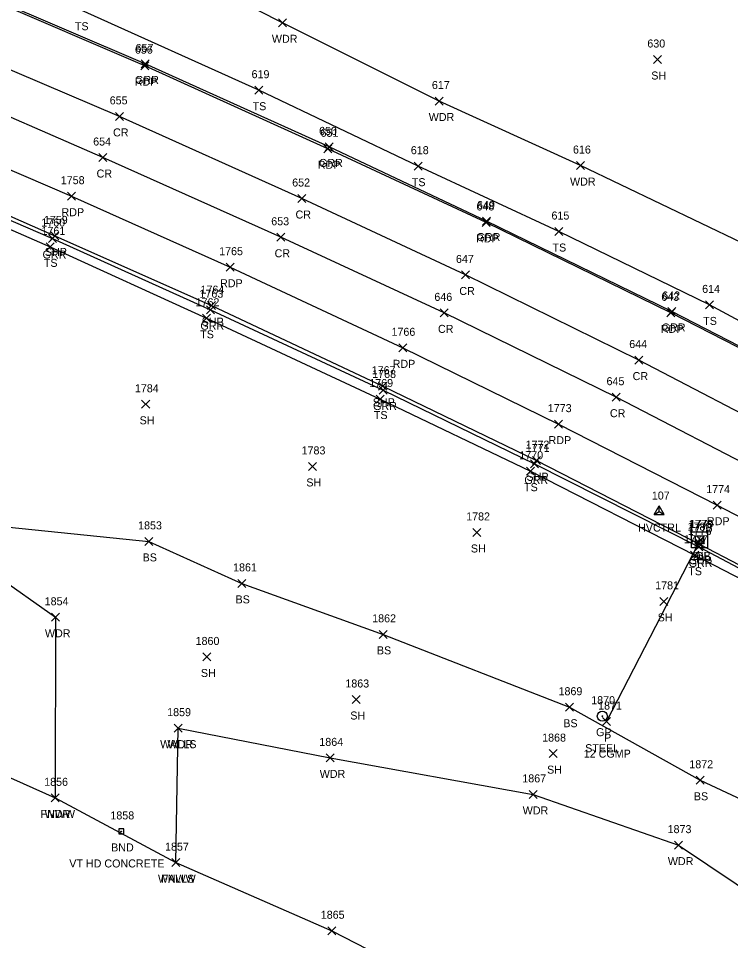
# Model space of a CAD drawing. Extents: x 1629176 to 1637209, y 606063 to 610167.
# Drawn here: x 1630257.8 to 1630435.7, y 606629.8 to 606860.2 of the extents above; entities that cross this region are included whole.
import ezdxf

# ---------------------------------------------------------------- set-up
doc = ezdxf.new("R2010")
doc.units = 0
for name, color, linetype in [('C_A', 7, 'Continuous'), ('C_I', 7, 'Continuous'), ('CPSM', 7, 'Continuous'), ('D_A', 7, 'Continuous'), ('D_C', 7, 'Continuous'), ('D_I', 7, 'Continuous'), ('D_TIC', 7, 'Continuous'), ('DCP', 7, 'Continuous'), ('DS', 7, 'Continuous'), ('L_A', 7, 'Continuous'), ('L_I', 7, 'Continuous'), ('L_TIC', 7, 'Continuous'), ('LAWA', 7, 'Continuous'), ('LELB', 7, 'Continuous'), ('LFNC', 7, 'Continuous'), ('LWS', 7, 'Continuous'), ('M_A', 7, 'Continuous'), ('M_C', 7, 'Continuous'), ('M_I', 7, 'Continuous'), ('MHBP', 7, 'Continuous'), ('P_A', 7, 'Continuous'), ('P_I', 7, 'Continuous'), ('P_TIC', 7, 'Continuous'), ('PET', 7, 'Continuous'), ('PRC', 7, 'Continuous'), ('PSP', 7, 'Continuous'), ('R_A', 7, 'Continuous'), ('R_C', 7, 'Continuous'), ('R_I', 7, 'Continuous'), ('R_TIC', 7, 'Continuous'), ('RGP', 7, 'Continuous'), ('RGR', 7, 'Continuous')]:
    doc.layers.add(name, color=color, linetype=linetype)

msp = doc.modelspace()

# ---------------------------------------------------------------- linework, layer by layer
at = {"layer": 'CPSM'}
for p, q in [((1630416.63, 606736.3), (1630417.88, 606738.46)), ((1630419.13, 606736.3), (1630417.88, 606738.46)), ((1630417.88, 606737.02), (1630417.88, 606738.46)), ((1630416.63, 606736.3), (1630417.88, 606737.02)), ((1630416.63, 606736.3), (1630419.13, 606736.3)), ((1630417.88, 606737.02), (1630417.88, 606737.02)), ((1630417.88, 606737.02), (1630419.13, 606736.3))]:
    msp.add_line(p, q, dxfattribs=at)
at = {"layer": 'D_TIC'}
for points in [[(1630427.15, 606728.94), (1630429.15, 606730.94)], [(1630429.15, 606728.94), (1630427.15, 606730.94)], [(1630426.71, 606728.26), (1630428.71, 606730.26)], [(1630428.71, 606728.26), (1630426.71, 606730.26)], [(1630403.72, 606683.54), (1630405.72, 606685.54)], [(1630405.72, 606683.54), (1630403.72, 606685.54)]]:
    msp.add_lwpolyline(points, dxfattribs=at)
at = {"layer": 'DCP'}
msp.add_lwpolyline([(1630427.71, 606729.26), (1630404.72, 606684.54)], dxfattribs=at)
at = {"layer": 'DS'}
for p, q in [((1630425.93, 606731.94), (1630429.93, 606731.94)), ((1630425.93, 606727.94), (1630425.93, 606731.94)), ((1630426.93, 606728.94), (1630426.93, 606730.94)), ((1630426.93, 606730.94), (1630428.93, 606730.94)), ((1630428.93, 606730.94), (1630428.93, 606728.94)), ((1630429.93, 606731.94), (1630429.93, 606727.94)), ((1630428.93, 606728.94), (1630426.93, 606728.94)), ((1630427.93, 606729.94), (1630427.93, 606729.94)), ((1630427.93, 606729.94), (1630427.93, 606729.94)), ((1630429.93, 606727.94), (1630425.93, 606727.94))]:
    msp.add_line(p, q, dxfattribs=at)
at = {"layer": 'L_TIC'}
for points in [[(1630322.76, 606858.13), (1630324.76, 606860.13)], [(1630324.76, 606858.13), (1630322.76, 606860.13)], [(1630416.39, 606848.96), (1630418.39, 606850.96)], [(1630418.39, 606848.96), (1630416.39, 606850.96)], [(1630316.9, 606841.29), (1630318.9, 606843.29)], [(1630318.9, 606841.29), (1630316.9, 606843.29)], [(1630361.92, 606838.59), (1630363.92, 606840.59)], [(1630363.92, 606838.59), (1630361.92, 606840.59)], [(1630356.66, 606822.31), (1630358.66, 606824.31)], [(1630358.66, 606822.31), (1630356.66, 606824.31)], [(1630397.22, 606822.46), (1630399.22, 606824.46)], [(1630399.22, 606822.46), (1630397.22, 606824.46)], [(1630391.8, 606805.98), (1630393.8, 606807.98)], [(1630393.8, 606805.98), (1630391.8, 606807.98)], [(1630264.76, 606802.15), (1630266.76, 606804.15)], [(1630266.76, 606802.15), (1630264.76, 606804.15)], [(1630429.43, 606787.65), (1630431.43, 606789.65)], [(1630431.43, 606787.65), (1630429.43, 606789.65)], [(1630303.81, 606784.31), (1630305.81, 606786.31)], [(1630305.81, 606784.31), (1630303.81, 606786.31)], [(1630347.18, 606764.13), (1630349.18, 606766.13)], [(1630349.18, 606764.13), (1630347.18, 606766.13)], [(1630288.6, 606762.82), (1630290.6, 606764.82)], [(1630290.6, 606762.82), (1630288.6, 606764.82)], [(1630330.23, 606747.3), (1630332.23, 606749.3)], [(1630332.23, 606747.3), (1630330.23, 606749.3)], [(1630384.69, 606746.11), (1630386.69, 606748.11)], [(1630386.69, 606746.11), (1630384.69, 606748.11)], [(1630371.34, 606730.8), (1630373.34, 606732.8)], [(1630373.34, 606730.8), (1630371.34, 606732.8)], [(1630289.4, 606728.57), (1630291.4, 606730.57)], [(1630291.4, 606728.57), (1630289.4, 606730.57)], [(1630425.71, 606725.12), (1630427.71, 606727.12)], [(1630427.71, 606725.12), (1630425.71, 606727.12)], [(1630312.6, 606718.08), (1630314.6, 606720.08)], [(1630314.6, 606718.08), (1630312.6, 606720.08)], [(1630417.98, 606713.59), (1630419.98, 606715.59)], [(1630419.98, 606713.59), (1630417.98, 606715.59)], [(1630266.08, 606709.61), (1630268.08, 606711.61)], [(1630268.08, 606709.61), (1630266.08, 606711.61)], [(1630347.91, 606705.34), (1630349.91, 606707.34)], [(1630349.91, 606705.34), (1630347.91, 606707.34)], [(1630303.9, 606699.7), (1630305.9, 606701.7)], [(1630305.9, 606699.7), (1630303.9, 606701.7)], [(1630341.21, 606689.07), (1630343.21, 606691.07)], [(1630343.21, 606689.07), (1630341.21, 606691.07)], [(1630394.46, 606687.14), (1630396.46, 606689.14)], [(1630396.46, 606687.14), (1630394.46, 606689.14)], [(1630296.68, 606681.91), (1630298.68, 606683.91)], [(1630298.68, 606681.91), (1630296.68, 606683.91)], [(1630296.68, 606681.91), (1630298.68, 606683.91)], [(1630298.68, 606681.91), (1630296.68, 606683.91)], [(1630390.36, 606675.55), (1630392.36, 606677.55)], [(1630392.36, 606675.55), (1630390.36, 606677.55)], [(1630334.71, 606674.48), (1630336.71, 606676.48)], [(1630336.71, 606674.48), (1630334.71, 606676.48)], [(1630427.07, 606668.89), (1630429.07, 606670.89)], [(1630429.07, 606668.89), (1630427.07, 606670.89)], [(1630266, 606664.5), (1630268, 606666.5)], [(1630268, 606664.5), (1630266, 606666.5)], [(1630266, 606664.5), (1630268, 606666.5)], [(1630268, 606664.5), (1630266, 606666.5)], [(1630385.4, 606665.36), (1630387.4, 606667.36)], [(1630387.4, 606665.36), (1630385.4, 606667.36)], [(1630421.65, 606652.68), (1630423.65, 606654.68)], [(1630423.65, 606652.68), (1630421.65, 606654.68)], [(1630296.13, 606648.31), (1630298.13, 606650.31)], [(1630298.13, 606648.31), (1630296.13, 606650.31)], [(1630296.13, 606648.31), (1630298.13, 606650.31)], [(1630298.13, 606648.31), (1630296.13, 606650.31)], [(1630335.07, 606631.29), (1630337.07, 606633.29)], [(1630337.07, 606631.29), (1630335.07, 606633.29)]]:
    msp.add_lwpolyline(points, dxfattribs=at)
at = {"layer": 'LAWA'}
for points in [[(1630313.82, 606946.86), (1630358.76, 606925.61), (1630402.3, 606903.75), (1630450.92, 606884.57), (1630493.61, 606863.97), (1630542.51, 606827.97), (1630547.78, 606801.97), (1630542.32, 606780.41), (1630525.99, 606758.91), (1630486.85, 606779.39), (1630438.5, 606804.18), (1630398.22, 606823.46), (1630362.92, 606839.59), (1630323.76, 606859.13), (1630280.39, 606881.23), (1630260.08, 606922.64), (1630278.57, 606959.7)], [(1630178.45, 606705.28), (1630189.54, 606725.28), (1630217.36, 606717.59), (1630251.89, 606721.32), (1630267.08, 606710.61), (1630267, 606665.5)], [(1630297.68, 606682.91), (1630335.71, 606675.48), (1630386.4, 606666.36), (1630422.65, 606653.68), (1630444.38, 606639.08), (1630446.66, 606637.81), (1630486.16, 606613.28), (1630514.89, 606608.05), (1630539.89, 606609.62), (1630562.09, 606603.08), (1630591.48, 606594.03), (1630626, 606578), (1630626.04, 606578.1), (1630670.33, 606553.73), (1630697.07, 606528.38), (1630722.88, 606501.58)]]:
    msp.add_lwpolyline(points, dxfattribs=at)
at = {"layer": 'LELB'}
for points in [[(1630772.3, 606583.26), (1630744.36, 606600.82), (1630702.09, 606628.01), (1630669.73, 606653.69), (1630639.16, 606677.6), (1630625.62, 606682.65), (1630575.5, 606708.79), (1630543.73, 606726.11), (1630517.88, 606742.14), (1630478.23, 606762.96), (1630430.43, 606788.65), (1630392.8, 606806.98), (1630357.66, 606823.31), (1630317.9, 606842.29), (1630273.51, 606862.27), (1630239.69, 606876.29), (1630209.67, 606888.82), (1630166.54, 606905.65), (1630125.1, 606921.22), (1630084.2, 606935.53), (1630049.16, 606947.36)], [(1630044.25, 606889.35), (1630091.41, 606872.59), (1630136.9, 606855.8), (1630181.87, 606838.43), (1630229.1, 606819.13), (1630265.76, 606803.15), (1630304.81, 606785.31), (1630348.18, 606765.13), (1630385.69, 606747.11), (1630426.71, 606726.12), (1630450.89, 606713.6)], [(1630053.59, 606794.16), (1630081.62, 606779.15), (1630106.52, 606768.08), (1630137.48, 606760.05), (1630167.15, 606751.57), (1630192.23, 606740.71), (1630218.23, 606736.11), (1630252.15, 606733.42), (1630290.4, 606729.57), (1630313.6, 606719.08), (1630348.91, 606706.34), (1630395.46, 606688.14), (1630428.07, 606669.89), (1630459.56, 606655.15)]]:
    msp.add_lwpolyline(points, dxfattribs=at)
at = {"layer": 'LFNC'}
msp.add_lwpolyline([(1630083.24, 606643.38), (1630104.82, 606668.58), (1630132.44, 606699.6), (1630148.03, 606717.8), (1630178.45, 606705.28), (1630206.32, 606692.67), (1630267, 606665.5), (1630297.13, 606649.31), (1630336.07, 606632.29), (1630377.56, 606610.95), (1630421.19, 606588.3), (1630449.11, 606572.58), (1630476.9, 606556.84), (1630504.46, 606540.78), (1630518.72, 606532.31), (1630544.56, 606516.77), (1630586.07, 606490.29), (1630617.62, 606470.71), (1630638.04, 606457.74), (1630683.84, 606426.78)], dxfattribs=at)
at = {"layer": 'LWS'}
msp.add_lwpolyline([(1630297.13, 606649.31), (1630297.68, 606682.91)], dxfattribs=at)
at = {"layer": 'MHBP'}
for p, q in [((1630284.13, 606657.77), (1630282.88, 606657.77)), ((1630282.88, 606657.77), (1630282.88, 606656.52)), ((1630284.13, 606657.77), (1630282.88, 606657.77)), ((1630282.88, 606657.77), (1630282.88, 606656.52)), ((1630284.13, 606656.52), (1630284.13, 606657.77)), ((1630284.13, 606656.52), (1630284.13, 606657.77)), ((1630282.88, 606656.52), (1630284.13, 606656.52)), ((1630282.88, 606656.52), (1630284.13, 606656.52))]:
    msp.add_line(p, q, dxfattribs=at)
msp.add_circle((1630283.48, 606657.11), 0.0833, dxfattribs=at)
at = {"layer": 'P_TIC'}
for points in [[(1630288.38, 606847.42), (1630290.38, 606849.42)], [(1630290.38, 606847.42), (1630288.38, 606849.42)], [(1630282.03, 606834.75), (1630284.03, 606836.75)], [(1630284.03, 606834.75), (1630282.03, 606836.75)], [(1630334.12, 606826.65), (1630336.12, 606828.65)], [(1630336.12, 606826.65), (1630334.12, 606828.65)], [(1630277.9, 606824.47), (1630279.9, 606826.47)], [(1630279.9, 606824.47), (1630277.9, 606826.47)], [(1630270.1, 606814.81), (1630272.1, 606816.81)], [(1630272.1, 606814.81), (1630270.1, 606816.81)], [(1630327.6, 606814.23), (1630329.6, 606816.23)], [(1630329.6, 606814.23), (1630327.6, 606816.23)], [(1630373.62, 606808.25), (1630375.62, 606810.25)], [(1630375.62, 606808.25), (1630373.62, 606810.25)], [(1630265.88, 606804.89), (1630267.88, 606806.89)], [(1630267.88, 606804.89), (1630265.88, 606806.89)], [(1630322.37, 606804.55), (1630324.37, 606806.55)], [(1630324.37, 606804.55), (1630322.37, 606806.55)], [(1630309.69, 606797.07), (1630311.69, 606799.07)], [(1630311.69, 606797.07), (1630309.69, 606799.07)], [(1630368.5, 606795.13), (1630370.5, 606797.13)], [(1630370.5, 606795.13), (1630368.5, 606797.13)], [(1630305.04, 606787.47), (1630307.04, 606789.47)], [(1630307.04, 606787.47), (1630305.04, 606789.47)], [(1630363.16, 606785.66), (1630365.16, 606787.66)], [(1630365.16, 606785.66), (1630363.16, 606787.66)], [(1630419.78, 606785.67), (1630421.78, 606787.67)], [(1630421.78, 606785.67), (1630419.78, 606787.67)], [(1630352.79, 606776.93), (1630354.79, 606778.93)], [(1630354.79, 606776.93), (1630352.79, 606778.93)], [(1630411.78, 606773.87), (1630413.78, 606775.87)], [(1630413.78, 606773.87), (1630411.78, 606775.87)], [(1630347.79, 606767.34), (1630349.79, 606769.34)], [(1630349.79, 606767.34), (1630347.79, 606769.34)], [(1630406.11, 606764.59), (1630408.11, 606766.59)], [(1630408.11, 606764.59), (1630406.11, 606766.59)], [(1630391.73, 606757.86), (1630393.73, 606759.86)], [(1630393.73, 606757.86), (1630391.73, 606759.86)], [(1630386.17, 606748.74), (1630388.17, 606750.74)], [(1630388.17, 606748.74), (1630386.17, 606750.74)], [(1630431.29, 606737.62), (1630433.29, 606739.62)], [(1630433.29, 606737.62), (1630431.29, 606739.62)], [(1630426.91, 606727.87), (1630428.91, 606729.87)], [(1630428.91, 606727.87), (1630426.91, 606729.87)]]:
    msp.add_lwpolyline(points, dxfattribs=at)
at = {"layer": 'PET'}
for points in [[(1630769.62, 606580.83), (1630742.32, 606598.72), (1630700.55, 606625.63), (1630665.45, 606648.34), (1630621.98, 606674.98), (1630606.18, 606684.39), (1630572.37, 606704.1), (1630541.12, 606722.17), (1630498.96, 606745.43), (1630457.51, 606767.81), (1630420.78, 606786.67), (1630374.62, 606809.25), (1630335.12, 606827.65), (1630289.38, 606848.42), (1630250.13, 606865.31), (1630203.69, 606884.49), (1630159.86, 606901.83), (1630115.59, 606918.47), (1630070.26, 606934.37)], [(1630050.76, 606901.68), (1630096.23, 606885.67), (1630143.35, 606868.08), (1630186.15, 606851.44), (1630235.05, 606831.31), (1630271.1, 606815.81), (1630310.69, 606798.07), (1630353.79, 606777.93), (1630392.73, 606758.86), (1630432.29, 606738.62), (1630464.02, 606722.09), (1630502.44, 606701.07), (1630537.98, 606680.83), (1630570.03, 606662.27), (1630609.11, 606638.58), (1630644.7, 606616.38), (1630681.38, 606592.72), (1630715.14, 606570.86), (1630750.81, 606547.81)]]:
    msp.add_lwpolyline(points, dxfattribs=at)
at = {"layer": 'PRC'}
for points in [[(1630762, 606568.31), (1630732.48, 606587.66), (1630693.14, 606613.4), (1630657.5, 606636.16), (1630615.44, 606661.97), (1630565.18, 606692.12), (1630533.4, 606710.56), (1630491.42, 606733.47), (1630450.45, 606755.19), (1630412.78, 606774.87), (1630369.5, 606796.13), (1630328.6, 606815.23), (1630283.03, 606835.75), (1630244.34, 606852.21), (1630197.18, 606871.73), (1630154.28, 606888.46), (1630110.18, 606905.77), (1630065.36, 606921.68)], [(1630755.45, 606559.52), (1630726, 606578.65), (1630686.27, 606604.3), (1630651.63, 606626.53), (1630610.5, 606651.79), (1630559.24, 606682.64), (1630527.45, 606700.94), (1630485.76, 606723.98), (1630445.96, 606745.41), (1630407.11, 606765.59), (1630364.16, 606786.66), (1630323.37, 606805.55), (1630278.9, 606825.47), (1630240.3, 606842.26), (1630192.63, 606861.5), (1630149.2, 606878.91), (1630105.99, 606894.95), (1630061.18, 606910.94)]]:
    msp.add_lwpolyline(points, dxfattribs=at)
at = {"layer": 'PSP'}
msp.add_lwpolyline([(1630045.28, 606892.75), (1630092.08, 606875.64), (1630138.49, 606858.75), (1630183.19, 606841.37), (1630230, 606822.13), (1630266.88, 606805.89), (1630306.04, 606788.47), (1630348.79, 606768.34), (1630387.17, 606749.74), (1630427.91, 606728.87), (1630457.64, 606713.36), (1630497.17, 606691.94), (1630531.87, 606672.45), (1630564.31, 606653.82), (1630602.72, 606629.92), (1630638.6, 606607.1), (1630675.39, 606583.77), (1630709.63, 606561.3), (1630744.78, 606538.28)], dxfattribs=at)
at = {"layer": 'R_TIC'}
for points in [[(1630288.48, 606847.85), (1630290.48, 606849.85)], [(1630290.48, 606847.85), (1630288.48, 606849.85)], [(1630334.39, 606827.12), (1630336.39, 606829.12)], [(1630336.39, 606827.12), (1630334.39, 606829.12)], [(1630373.76, 606808.6), (1630375.76, 606810.6)], [(1630375.76, 606808.6), (1630373.76, 606810.6)], [(1630265.36, 606804.24), (1630267.36, 606806.24)], [(1630267.36, 606804.24), (1630265.36, 606806.24)], [(1630304.77, 606786.45), (1630306.77, 606788.45)], [(1630306.77, 606786.45), (1630304.77, 606788.45)], [(1630420.01, 606786.01), (1630422.01, 606788.01)], [(1630422.01, 606786.01), (1630420.01, 606788.01)], [(1630347.91, 606766.39), (1630349.91, 606768.39)], [(1630349.91, 606766.39), (1630347.91, 606768.39)], [(1630385.68, 606747.91), (1630387.68, 606749.91)], [(1630387.68, 606747.91), (1630385.68, 606749.91)], [(1630426.72, 606727.18), (1630428.72, 606729.18)], [(1630428.72, 606727.18), (1630426.72, 606729.18)]]:
    msp.add_lwpolyline(points, dxfattribs=at)
at = {"layer": 'RGP'}
msp.add_line((1630403.65, 606685.9), (1630403.65, 606685.9), dxfattribs=at)
for radius in [1.25, 0.0833]:
    msp.add_circle((1630403.65, 606685.9), radius, dxfattribs=at)
at = {"layer": 'RGR'}
for points in [[(1630636.53, 606670.83), (1630623.24, 606676.36), (1630606.52, 606684.67), (1630573.19, 606704.3), (1630541.55, 606722.4), (1630499.19, 606745.82), (1630457.55, 606768.16), (1630421.01, 606787.01), (1630374.76, 606809.6), (1630335.39, 606828.12), (1630289.48, 606848.85), (1630250.07, 606865.82), (1630203.7, 606885.03), (1630160.01, 606902.28), (1630115.67, 606918.76), (1630070.66, 606934.74)], [(1630044.87, 606891.43), (1630091.95, 606875), (1630137.84, 606857.9), (1630182.67, 606840.57), (1630230.01, 606820.88), (1630266.36, 606805.24), (1630305.77, 606787.45), (1630348.91, 606767.39), (1630386.68, 606748.91), (1630427.72, 606728.18), (1630457.43, 606712.48), (1630496.65, 606691.24), (1630531.18, 606671.77), (1630563.73, 606652.86), (1630574.41, 606646.66), (1630584.49, 606638.94), (1630594.27, 606630.4)]]:
    msp.add_lwpolyline(points, dxfattribs=at)

# ---------------------------------------------------------------- texts
at = {"layer": 'C_A'}
msp.add_text('HVCTRL', height=2, dxfattribs=at).set_placement((1630412.58, 606732.02))
at = {"layer": 'C_I'}
msp.add_text('107', height=2, dxfattribs=at).set_placement((1630416.01, 606740.02))
at = {"layer": 'D_A'}
for s, p in [('DIB', (1630426.25, 606724.94)), ('DI', (1630426.99, 606724.94)), ('P', (1630427.08, 606724.26)), ('P', (1630404.09, 606679.54))]:
    msp.add_text(s, height=2, dxfattribs=at).set_placement(p)
at = {"layer": 'D_C'}
msp.add_text('12 CGMP', height=2, dxfattribs=at).set_placement((1630399.01, 606675.54))
at = {"layer": 'D_I'}
for s, p in [('1778', (1630425.24, 606732.94)), ('1779', (1630425.45, 606732.94)), ('1780', (1630424.93, 606732.26)), ('1871', (1630402.59, 606687.54))]:
    msp.add_text(s, height=2, dxfattribs=at).set_placement(p)
at = {"layer": 'L_A'}
for s, p in [('TS', (1630271.92, 606857.27)), ('WDR', (1630321.12, 606854.13)), ('SH', (1630415.87, 606844.96)), ('TS', (1630316.31, 606837.29)), ('WDR', (1630360.29, 606834.59)), ('TS', (1630356.07, 606818.31)), ('WDR', (1630395.58, 606818.46)), ('TS', (1630391.21, 606801.98)), ('TS', (1630264.17, 606798.15)), ('TS', (1630428.84, 606783.65)), ('TS', (1630303.22, 606780.31)), ('SH', (1630288.09, 606758.82)), ('TS', (1630346.59, 606760.13)), ('SH', (1630329.72, 606743.3)), ('TS', (1630384.1, 606742.11)), ('SH', (1630370.82, 606726.8)), ('BS', (1630288.84, 606724.57)), ('TS', (1630425.12, 606721.12)), ('BS', (1630312.04, 606714.08)), ('SH', (1630417.47, 606709.59)), ('WDR', (1630264.44, 606705.61)), ('BS', (1630347.35, 606701.34)), ('SH', (1630303.39, 606695.7)), ('SH', (1630340.7, 606685.07)), ('BS', (1630393.9, 606683.14)), ('WALLS', (1630293.22, 606677.91)), ('WDR', (1630295.04, 606677.91)), ('SH', (1630389.85, 606671.55)), ('WDR', (1630333.07, 606670.48)), ('BS', (1630426.51, 606664.89)), ('FNWW', (1630263.35, 606660.5)), ('WDR', (1630264.36, 606660.5)), ('WDR', (1630383.76, 606661.36)), ('WDR', (1630420.01, 606648.68)), ('WALLS', (1630292.67, 606644.31)), ('FNWW', (1630293.48, 606644.31))]:
    msp.add_text(s, height=2, dxfattribs=at).set_placement(p)
at = {"layer": 'L_I'}
for s, p in [('630', (1630414.89, 606852.96)), ('619', (1630316.05, 606845.29)), ('617', (1630361.08, 606842.59)), ('618', (1630355.82, 606826.31)), ('616', (1630396.32, 606826.46)), ('615', (1630390.95, 606809.98)), ('1761', (1630263.59, 606806.15)), ('614', (1630428.58, 606791.65)), ('1762', (1630302.07, 606788.31)), ('1769', (1630345.44, 606768.13)), ('1784', (1630286.91, 606766.82)), ('1783', (1630328.54, 606751.3)), ('1770', (1630382.91, 606750.11)), ('1782', (1630369.64, 606734.8)), ('1853', (1630287.71, 606732.57)), ('1777', (1630424.02, 606729.12)), ('1861', (1630311.43, 606722.08)), ('1781', (1630416.85, 606717.59)), ('1854', (1630264.38, 606713.61)), ('1862', (1630346.17, 606709.34)), ('1860', (1630302.07, 606703.7)), ('1863', (1630339.47, 606693.07)), ('1869', (1630392.71, 606691.14)), ('1859', (1630294.97, 606685.91)), ('1859', (1630294.97, 606685.91)), ('1864', (1630332.97, 606678.48)), ('1868', (1630388.62, 606679.55)), ('1872', (1630425.38, 606672.89)), ('1856', (1630264.25, 606668.5)), ('1856', (1630264.25, 606668.5)), ('1867', (1630383.66, 606669.36)), ('1873', (1630419.95, 606656.68)), ('1857', (1630294.44, 606652.31)), ('1857', (1630294.44, 606652.31)), ('1865', (1630333.33, 606635.29))]:
    msp.add_text(s, height=2, dxfattribs=at).set_placement(p)
at = {"layer": 'M_A'}
msp.add_text('BND', height=2, dxfattribs=at).set_placement((1630280.97, 606652.11))
at = {"layer": 'M_C'}
msp.add_text('VT HD CONCRETE', height=2, dxfattribs=at).set_placement((1630270.52, 606648.11))
at = {"layer": 'M_I'}
msp.add_text('1858', height=2, dxfattribs=at).set_placement((1630280.79, 606660.11))
at = {"layer": 'P_A'}
for s, p in [('RDP', (1630286.86, 606843.42)), ('CR', (1630281.46, 606830.75)), ('CR', (1630277.34, 606820.47)), ('RDP', (1630332.6, 606822.65)), ('RDP', (1630268.59, 606810.81)), ('CR', (1630327.03, 606810.23)), ('RDP', (1630372.11, 606804.25)), ('SHP', (1630264.42, 606800.89)), ('CR', (1630321.8, 606800.55)), ('RDP', (1630308.18, 606793.07)), ('CR', (1630367.93, 606791.13)), ('SHP', (1630303.58, 606783.47)), ('CR', (1630362.6, 606781.66)), ('RDP', (1630418.27, 606781.67)), ('RDP', (1630351.28, 606772.93)), ('CR', (1630411.21, 606769.87)), ('SHP', (1630346.32, 606763.34)), ('CR', (1630405.54, 606760.59)), ('RDP', (1630390.22, 606753.86)), ('SHP', (1630384.71, 606744.74)), ('RDP', (1630429.77, 606733.62)), ('SHP', (1630425.45, 606723.87))]:
    msp.add_text(s, height=2, dxfattribs=at).set_placement(p)
at = {"layer": 'P_I'}
for s, p in [('656', (1630286.91, 606851.42)), ('655', (1630280.62, 606838.75)), ('651', (1630333.27, 606830.65)), ('654', (1630276.49, 606828.47)), ('1758', (1630268.4, 606818.81)), ('652', (1630326.19, 606818.23)), ('648', (1630372.21, 606812.25)), ('1759', (1630264.18, 606808.89)), ('653', (1630320.96, 606808.55)), ('1765', (1630307.95, 606801.07)), ('647', (1630367.09, 606799.13)), ('1764', (1630303.3, 606791.47)), ('646', (1630361.7, 606789.66)), ('643', (1630418.37, 606789.67)), ('1766', (1630350.99, 606780.93)), ('644', (1630410.37, 606777.87)), ('1767', (1630346.05, 606771.34)), ('645', (1630404.7, 606768.59)), ('1773', (1630390.03, 606761.86)), ('1772', (1630384.48, 606752.74)), ('1774', (1630429.59, 606741.62)), ('1775', (1630425.22, 606731.87))]:
    msp.add_text(s, height=2, dxfattribs=at).set_placement(p)
at = {"layer": 'R_A'}
for s, p in [('GRR', (1630286.97, 606843.85)), ('GRR', (1630332.88, 606823.12)), ('GRR', (1630372.25, 606804.6)), ('GRR', (1630263.85, 606800.24)), ('GRR', (1630303.26, 606782.45)), ('GRR', (1630418.5, 606782.01)), ('GRR', (1630346.4, 606762.39)), ('GRR', (1630384.17, 606743.91)), ('GRR', (1630425.21, 606723.18)), ('GP', (1630402.08, 606680.9))]:
    msp.add_text(s, height=2, dxfattribs=at).set_placement(p)
at = {"layer": 'R_C'}
msp.add_text('STEEL', height=2, dxfattribs=at).set_placement((1630399.36, 606676.9))
at = {"layer": 'R_I'}
for s, p in [('657', (1630287.07, 606851.85)), ('650', (1630332.9, 606831.12)), ('649', (1630372.34, 606812.6)), ('1760', (1630263.54, 606808.24)), ('1763', (1630303.03, 606790.45)), ('642', (1630418.6, 606790.01)), ('1768', (1630346.17, 606770.39)), ('1771', (1630384.55, 606751.91)), ('1776', (1630424.97, 606731.18)), ('1870', (1630400.87, 606688.9))]:
    msp.add_text(s, height=2, dxfattribs=at).set_placement(p)

doc.saveas('drawing.dxf')
